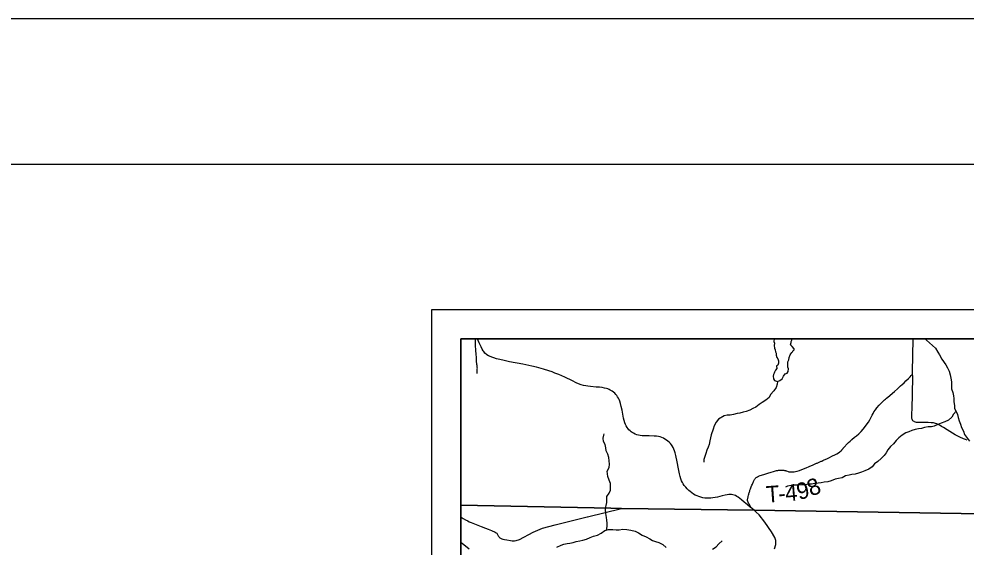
# Model space of a CAD drawing. Extents: x 0 to 34, y 0 to 22.
# Drawn here: x 21.997 to 25.254, y 20.183 to 22 of the extents above; entities that cross this region are included whole.
import ezdxf

# ---------------------------------------------------------------- set-up
doc = ezdxf.new("R2010")
doc.units = 0
for name, color, linetype in [('GM_X_Corporation', 7, 'Continuous'), ('GM_X_Minor_Lake', 7, 'Continuous'), ('GM_X_Minor_River', 7, 'Continuous'), ('GM_X_State_Route', 7, 'Continuous'), ('GM_X_Township_Road', 7, 'Continuous'), ('GM_X_Township_Road_Text', 7, 'Continuous'), ('SH_Border', 7, 'Continuous'), ('SH_Cut_Line', 7, 'Continuous'), ('SH_Data', 7, 'Continuous')]:
    doc.layers.add(name, color=color, linetype=linetype)

msp = doc.modelspace()

# ---------------------------------------------------------------- linework, layer by layer
at = {"layer": 'GM_X_Corporation'}
msp.add_lwpolyline([(27.1022, 20.9), (23.5167, 20.9), (23.5167, 20.3276), (24.0328, 20.3169), (24.0688, 20.3165), (24.5249, 20.3107), (25.4507, 20.2949), (26.2533, 20.2773), (26.5702, 20.276), (26.6351, 20.2734), (26.7196, 20.2707), (26.7822, 20.2704), (27.0031, 20.2673), (27.0873, 20.2665), (27.089, 20.3692), (27.0897, 20.4135), (27.0898, 20.417)], close=True, dxfattribs=at)
msp.add_lwpolyline([(27.1022, 20.9), (23.5167, 20.9), (23.5167, 20.3276), (24.0328, 20.3169), (24.0688, 20.3165), (24.5249, 20.3107), (25.4507, 20.2949), (26.2533, 20.2773), (26.5702, 20.276), (26.6351, 20.2734), (26.7196, 20.2707), (26.7822, 20.2704), (27.0031, 20.2673), (27.0873, 20.2665), (27.089, 20.3692), (27.0897, 20.4135), (27.0898, 20.417)], close=True, dxfattribs=at)
msp.add_lwpolyline([(27.0234, 16.6611), (27.0349, 17.5522), (27.0419, 17.8236), (27.0487, 18.5805), (27.0719, 19.3912), (27.0733, 19.498), (27.0761, 19.6806), (27.0864, 20.0138), (27.0885, 20.1139), (27.0907, 20.123), (27.0873, 20.2665), (27.0031, 20.2673), (26.7822, 20.2704), (26.7196, 20.2707), (26.6351, 20.2734), (26.5702, 20.276), (26.2533, 20.2773), (25.4507, 20.2949), (24.5249, 20.3107), (24.0688, 20.3165), (24.0328, 20.3169), (23.5167, 20.3276), (23.5167, 14.5642)], dxfattribs=at)
msp.add_lwpolyline([(27.0234, 16.6611), (27.0349, 17.5522), (27.0419, 17.8236), (27.0487, 18.5805), (27.0719, 19.3912), (27.0733, 19.498), (27.0761, 19.6806), (27.0864, 20.0138), (27.0885, 20.1139), (27.0907, 20.123), (27.0873, 20.2665), (27.0031, 20.2673), (26.7822, 20.2704), (26.7196, 20.2707), (26.6351, 20.2734), (26.5702, 20.276), (26.2533, 20.2773), (25.4507, 20.2949), (24.5249, 20.3107), (24.0688, 20.3165), (24.0328, 20.3169), (23.5167, 20.3276), (23.5167, 14.5642)], dxfattribs=at)
at = {"layer": 'GM_X_Minor_Lake'}
for points in [[(24.5943, 20.9), (24.593, 20.89), (24.5953, 20.8844), (24.5946, 20.8764), (24.5951, 20.8677), (24.597, 20.8613), (24.599, 20.8544), (24.6009, 20.8499), (24.6006, 20.8438), (24.603, 20.8359), (24.6072, 20.8303), (24.6091, 20.8238), (24.6092, 20.8163), (24.607, 20.809), (24.6036, 20.8063), (24.6021, 20.8052), (24.6033, 20.7972), (24.5992, 20.7915), (24.5948, 20.7853), (24.5937, 20.7815), (24.5918, 20.777), (24.5911, 20.7713), (24.5916, 20.7622), (24.5954, 20.7561), (24.6053, 20.7528)], [(24.6053, 20.7528), (24.614, 20.756), (24.6215, 20.7621), (24.6259, 20.7717), (24.6319, 20.7797), (24.6387, 20.781), (24.6417, 20.7867), (24.6431, 20.7966), (24.6415, 20.8019), (24.641, 20.8163), (24.6406, 20.8208), (24.6443, 20.8273), (24.6457, 20.8349), (24.649, 20.8441), (24.6513, 20.8475), (24.655, 20.8525), (24.6569, 20.8548), (24.6599, 20.8598), (24.6625, 20.8613), (24.6628, 20.8647), (24.6556, 20.8734), (24.6506, 20.8794), (24.6524, 20.8866), (24.6531, 20.8904), (24.6546, 20.895), (24.6552, 20.9)]]:
    msp.add_lwpolyline(points, dxfattribs=at)
at = {"layer": 'GM_X_Minor_River'}
for points in [[(25.113, 20.9), (25.1178, 20.8946), (25.1281, 20.8857), (25.1388, 20.8771), (25.1487, 20.8669), (25.1571, 20.8538), (25.1629, 20.844), (25.171, 20.83), (25.1841, 20.8105), (25.1899, 20.7999), (25.196, 20.7879), (25.1996, 20.7758), (25.2019, 20.764), (25.204, 20.7515), (25.2037, 20.7379), (25.2042, 20.728), (25.2089, 20.7155), (25.2109, 20.7034), (25.2114, 20.6939), (25.2115, 20.6829), (25.2139, 20.6697), (25.2147, 20.6602), (25.2201, 20.6497), (25.224, 20.6391), (25.2264, 20.6285), (25.2307, 20.6179), (25.2349, 20.6062), (25.2388, 20.5941), (25.245, 20.5817), (25.2489, 20.5703), (25.2654, 20.5478)], [(24.6053, 20.7528), (24.6039, 20.7433), (24.6006, 20.7327), (24.5924, 20.7212), (24.5815, 20.7078), (24.5767, 20.6975), (24.5658, 20.6882), (24.5527, 20.6808), (24.5422, 20.6735), (24.5316, 20.6646), (24.5207, 20.6603), (24.5109, 20.6538), (24.4981, 20.6498), (24.4879, 20.6474), (24.4766, 20.6439), (24.4664, 20.6422), (24.4547, 20.6398), (24.443, 20.637), (24.432, 20.6365), (24.4222, 20.6352), (24.4027, 20.6228), (24.3948, 20.6129), (24.3881, 20.6006), (24.3845, 20.5888), (24.3778, 20.569), (24.3749, 20.5591), (24.3724, 20.5484), (24.3702, 20.5366), (24.3669, 20.5264), (24.3629, 20.5161), (24.3588, 20.505), (24.3559, 20.4947), (24.3526, 20.4841), (24.3527, 20.4757)], [(25.2195, 20.6509), (25.2111, 20.6408), (25.2048, 20.6305), (25.1932, 20.6197), (25.1804, 20.6135), (25.1683, 20.6092), (25.157, 20.6045), (25.1446, 20.5994), (25.1348, 20.5974), (25.1238, 20.5972), (25.1109, 20.5944), (25.1011, 20.5909), (25.0902, 20.5904), (25.0785, 20.588), (25.0679, 20.5848), (25.057, 20.5797), (25.0464, 20.5762), (25.034, 20.5681), (25.0228, 20.5592), (25.0141, 20.5496), (25.004, 20.5388), (24.9939, 20.5296), (24.985, 20.5174), (24.9794, 20.5078), (24.9719, 20.4982), (24.9625, 20.4879), (24.9505, 20.4775), (24.9393, 20.4694), (24.9307, 20.4598), (24.9194, 20.4517), (24.9062, 20.4454), (24.8949, 20.4407), (24.884, 20.4372), (24.8723, 20.434), (24.8617, 20.4327), (24.8515, 20.4303), (24.8394, 20.4279), (24.8278, 20.4213), (24.8157, 20.4196), (24.8036, 20.4168), (24.7896, 20.4113), (24.7791, 20.4074), (24.7666, 20.4065), (24.7557, 20.4045), (24.7454, 20.4036), (24.7337, 20.4015), (24.7224, 20.4002), (24.7114, 20.3997), (24.7016, 20.3977), (24.688, 20.3975), (24.6766, 20.3963), (24.6623, 20.3961), (24.6524, 20.3948), (24.6396, 20.3928), (24.6328, 20.3896)], [(24.0147, 20.3169), (24.0167, 20.3267), (24.0183, 20.3369), (24.0187, 20.347), (24.0186, 20.3573), (24.0268, 20.3688), (24.0316, 20.3787), (24.0308, 20.3905), (24.0314, 20.4022), (24.0268, 20.4132), (24.0221, 20.4264), (24.0204, 20.4442), (24.0271, 20.4572), (24.0281, 20.469), (24.0265, 20.4796), (24.026, 20.4917), (24.0217, 20.5023), (24.0167, 20.514), (24.0154, 20.5246), (24.0126, 20.536), (24.0076, 20.5465), (24.0064, 20.5583), (24.0082, 20.5682), (24.0092, 20.5727)], [(24.0181, 20.2416), (24.0197, 20.2545), (24.02, 20.2651), (24.0192, 20.2754), (24.0177, 20.2849), (24.0154, 20.2986), (24.0146, 20.3115), (24.0147, 20.3169)], [(23.8472, 20.1825), (23.8612, 20.1901), (23.8707, 20.1932), (23.8821, 20.1955), (23.8915, 20.1971), (23.9033, 20.1994), (23.9132, 20.2025), (23.9257, 20.2048), (23.9359, 20.2071), (23.9484, 20.2106), (23.9613, 20.2159), (23.9727, 20.2205), (23.9863, 20.224), (23.9992, 20.2316), (24.0113, 20.2397), (24.0246, 20.2435), (24.039, 20.2432), (24.0508, 20.2421), (24.0607, 20.2429), (24.0743, 20.2452), (24.0872, 20.2441), (24.1009, 20.2415), (24.1161, 20.2374), (24.1279, 20.2321), (24.1408, 20.2238), (24.1541, 20.2185), (24.1666, 20.2121), (24.1761, 20.206), (24.1864, 20.2023), (24.1978, 20.1989), (24.2114, 20.1917), (24.2232, 20.1823)], [(23.5167, 20.2001), (23.5224, 20.1958), (23.5322, 20.1878), (23.5455, 20.1776)], [(24.3818, 20.176), (24.3943, 20.1844), (24.4042, 20.1947), (24.4148, 20.205)]]:
    msp.add_lwpolyline(points, dxfattribs=at)
at = {"layer": 'GM_X_State_Route'}
for points in [[(24.5145, 20.3186), (24.513, 20.3197), (24.5029, 20.328), (24.4912, 20.3382), (24.4823, 20.3459), (24.4765, 20.3505), (24.4709, 20.3544), (24.4657, 20.3576), (24.4608, 20.3601), (24.4562, 20.3618), (24.4515, 20.3631), (24.4473, 20.3637), (24.4437, 20.3639), (24.4388, 20.3638), (24.4327, 20.3631), (24.4261, 20.3619), (24.4152, 20.3592), (24.3995, 20.3552), (24.391, 20.3534), (24.383, 20.3522), (24.3761, 20.3515), (24.3699, 20.3513), (24.3624, 20.3514), (24.3555, 20.352), (24.3493, 20.3529), (24.342, 20.3547), (24.3354, 20.3568), (24.3291, 20.3594), (24.3228, 20.3623), (24.3169, 20.3657), (24.3106, 20.3698), (24.3051, 20.374), (24.3004, 20.378), (24.2951, 20.3833), (24.2901, 20.3889), (24.2851, 20.3953), (24.2816, 20.4005), (24.2784, 20.4059), (24.2757, 20.4115), (24.2729, 20.4185), (24.2707, 20.4257), (24.2684, 20.4354), (24.2651, 20.4519), (24.2604, 20.4769), (24.2561, 20.4982), (24.2538, 20.5072), (24.2516, 20.5142), (24.2492, 20.5205), (24.2465, 20.5261), (24.2435, 20.5314), (24.2407, 20.5355), (24.2377, 20.5393), (24.2334, 20.5437), (24.2288, 20.5477), (24.2239, 20.5514), (24.2187, 20.5547), (24.2133, 20.5576), (24.2082, 20.5599), (24.2025, 20.5619), (24.1965, 20.5634), (24.1899, 20.5645), (24.1813, 20.5651), (24.1645, 20.5656), (24.1465, 20.5659), (24.1403, 20.5663), (24.1334, 20.5671), (24.1273, 20.5684), (24.1218, 20.5699), (24.1165, 20.5719), (24.1108, 20.5745), (24.1064, 20.577), (24.1023, 20.5798), (24.0984, 20.583), (24.0948, 20.5866), (24.0916, 20.5904), (24.0883, 20.5951), (24.0854, 20.5999), (24.0832, 20.6045), (24.0807, 20.6109), (24.0784, 20.6181), (24.0764, 20.6266), (24.071, 20.654), (24.0682, 20.6667), (24.0655, 20.6769), (24.0629, 20.6852), (24.0607, 20.6909), (24.0583, 20.6959), (24.0555, 20.7006), (24.0528, 20.7046), (24.0497, 20.7084), (24.0458, 20.7123), (24.0417, 20.7159), (24.0367, 20.7195), (24.0305, 20.7234), (24.0262, 20.7256), (24.0223, 20.7272), (24.0171, 20.7288), (24.0106, 20.7304), (24.0027, 20.7319), (23.993, 20.7329), (23.9825, 20.7337), (23.9627, 20.7352), (23.9534, 20.7363), (23.9461, 20.7375), (23.9382, 20.7393), (23.9304, 20.7417), (23.9217, 20.745), (23.9131, 20.7487), (23.9002, 20.7549), (23.8741, 20.7678), (23.864, 20.7725), (23.8532, 20.7771), (23.8405, 20.782), (23.8306, 20.7855), (23.8189, 20.7894), (23.8011, 20.7948), (23.7772, 20.8016), (23.7611, 20.8059), (23.7508, 20.8083), (23.7295, 20.8125), (23.6837, 20.8209), (23.6654, 20.8246), (23.6509, 20.828), (23.6394, 20.8311), (23.6299, 20.834), (23.6234, 20.8363), (23.6153, 20.8396), (23.6114, 20.8416), (23.6065, 20.8446), (23.6036, 20.847), (23.5998, 20.8503), (23.5955, 20.8557), (23.5938, 20.8583), (23.5905, 20.8644), (23.5865, 20.872), (23.58, 20.8862), (23.5763, 20.8942), (23.5736, 20.9)], [(24.5251, 20.3101), (24.5194, 20.3149), (24.5145, 20.3186)], [(24.5953, 20.1775), (24.5993, 20.1917), (24.6004, 20.1987), (24.5998, 20.2058), (24.5969, 20.2163), (24.5849, 20.2359), (24.5615, 20.2694), (24.5427, 20.2943), (24.5326, 20.3034), (24.5251, 20.3101)]]:
    msp.add_lwpolyline(points, dxfattribs=at)
at = {"layer": 'GM_X_Township_Road'}
msp.add_line((23.9522, 20.2872), (24.069, 20.3159), dxfattribs=at)
for points in [[(23.5723, 20.7801), (23.573, 20.7891), (23.5732, 20.7926), (23.5734, 20.7952), (23.5735, 20.7981), (23.5734, 20.8008), (23.5731, 20.8042), (23.5728, 20.8071), (23.5725, 20.809), (23.5722, 20.8106), (23.572, 20.8119), (23.5718, 20.813), (23.5715, 20.8144), (23.5713, 20.8157), (23.5709, 20.8178), (23.5707, 20.8196), (23.5705, 20.821), (23.5704, 20.8226), (23.5704, 20.8242), (23.5703, 20.8258), (23.5703, 20.8271), (23.5703, 20.8291), (23.5701, 20.839), (23.5699, 20.8438), (23.5686, 20.8625), (23.5675, 20.8742), (23.567, 20.8842), (23.5669, 20.8923), (23.5671, 20.895), (23.5673, 20.8978), (23.5675, 20.8997), (23.5676, 20.9)], [(25.0702, 20.7781), (25.07, 20.79), (25.0703, 20.8087), (25.0704, 20.8192), (25.0708, 20.8316), (25.0711, 20.8459), (25.0712, 20.8515), (25.0714, 20.8658), (25.0716, 20.8745), (25.0716, 20.8825), (25.0717, 20.8875), (25.0718, 20.8966), (25.0719, 20.8997), (25.0719, 20.9)], [(24.5145, 20.3186), (24.5125, 20.3231), (24.5116, 20.325), (24.51, 20.3277), (24.5082, 20.3309), (24.5058, 20.3345), (24.5044, 20.3372), (24.5034, 20.3401), (24.5028, 20.3432), (24.5028, 20.3448), (24.5028, 20.3469), (24.5029, 20.3486), (24.5032, 20.3506), (24.5037, 20.3529), (24.5042, 20.3554), (24.5048, 20.3576), (24.5059, 20.3616), (24.5067, 20.3647), (24.5074, 20.3671), (24.5082, 20.37), (24.5089, 20.3727), (24.51, 20.3761), (24.5109, 20.3788), (24.5117, 20.3817), (24.5126, 20.384), (24.5139, 20.3874), (24.5152, 20.3908), (24.5173, 20.396), (24.5191, 20.4), (24.5202, 20.4028), (24.5214, 20.4055), (24.5226, 20.4086), (24.5239, 20.4109), (24.5252, 20.4135), (24.5264, 20.4153), (24.5275, 20.4172), (24.5288, 20.4188), (24.5304, 20.4204), (24.5321, 20.4221), (24.5341, 20.4236), (24.5368, 20.4252), (24.5401, 20.4268), (24.5459, 20.429), (24.5589, 20.4331), (24.572, 20.437), (24.5762, 20.4382), (24.5809, 20.4396), (24.5951, 20.4441), (24.6017, 20.4461), (24.605, 20.4468), (24.6071, 20.4471), (24.609, 20.4474), (24.6119, 20.4477), (24.6148, 20.4478), (24.618, 20.4479), (24.622, 20.4479), (24.6244, 20.4478), (24.6269, 20.4475), (24.6297, 20.4471), (24.6326, 20.4464), (24.6344, 20.4458), (24.637, 20.445), (24.6422, 20.4434), (24.6451, 20.4426), (24.6482, 20.442), (24.6528, 20.4416), (24.6576, 20.4416), (24.663, 20.442), (24.6672, 20.4428), (24.6732, 20.4443), (24.6809, 20.4467), (24.689, 20.4497), (24.7045, 20.4562), (24.7147, 20.4607), (24.7284, 20.4666), (24.7396, 20.4714), (24.7419, 20.4724), (24.7441, 20.4734), (24.7469, 20.4746), (24.7491, 20.4756), (24.7509, 20.4764), (24.7531, 20.4773), (24.7554, 20.4783), (24.7576, 20.4793), (24.7616, 20.4811), (24.7666, 20.4834), (24.7748, 20.4872), (24.7798, 20.4894), (24.7841, 20.4915), (24.7925, 20.4957), (24.797, 20.4979), (24.8002, 20.4995), (24.8048, 20.5018), (24.8093, 20.5045), (24.8148, 20.5077), (24.8196, 20.511), (24.8227, 20.5134), (24.8254, 20.5157), (24.8269, 20.5172), (24.8278, 20.5182), (24.8285, 20.5191), (24.8292, 20.52), (24.8302, 20.5211), (24.831, 20.5221), (24.8318, 20.5232), (24.8328, 20.5245), (24.8354, 20.5276), (24.8378, 20.5303), (24.8394, 20.5319), (24.8409, 20.5337), (24.8434, 20.5363), (24.8465, 20.5393), (24.8498, 20.5429), (24.8552, 20.5481), (24.8584, 20.5511), (24.8612, 20.5536), (24.8704, 20.5608), (24.8767, 20.5657), (24.885, 20.5723), (24.8891, 20.576), (24.8934, 20.5805), (24.9006, 20.5891), (24.9083, 20.5988), (24.9141, 20.6068), (24.9182, 20.613), (24.923, 20.621), (24.9313, 20.6369), (24.934, 20.6425), (24.9354, 20.6452), (24.9373, 20.6484), (24.9421, 20.6555), (24.9471, 20.6618), (24.9557, 20.6715), (24.9582, 20.6743), (24.9623, 20.6788), (24.9663, 20.6826), (24.974, 20.6897), (24.9767, 20.6921), (24.98, 20.6949), (24.9852, 20.6992), (24.9914, 20.7043), (25.0009, 20.7122), (25.0074, 20.7179), (25.0182, 20.7278), (25.0286, 20.7374), (25.0345, 20.7427), (25.0408, 20.7486), (25.0474, 20.755), (25.0557, 20.7633), (25.0613, 20.7691), (25.0656, 20.7735), (25.0702, 20.7781)], [(25.2577, 20.551), (25.2518, 20.5529), (25.2449, 20.5556), (25.2329, 20.5609), (25.2234, 20.5656), (25.2169, 20.5691), (25.2073, 20.5748), (25.1889, 20.5864), (25.1763, 20.5944), (25.17, 20.5983), (25.1652, 20.6012), (25.1586, 20.6046), (25.1534, 20.6068), (25.1488, 20.6084), (25.1454, 20.6093), (25.1421, 20.6101), (25.1385, 20.6106), (25.1342, 20.6109), (25.1236, 20.6112), (25.1106, 20.6114), (25.0957, 20.6116), (25.0907, 20.6118), (25.0876, 20.6119), (25.0839, 20.6122), (25.0802, 20.6129), (25.0772, 20.6137), (25.075, 20.6147), (25.0729, 20.6162), (25.0712, 20.6179), (25.0698, 20.6199), (25.0685, 20.6227), (25.0678, 20.6251), (25.0674, 20.6275), (25.0673, 20.6294), (25.0672, 20.6312), (25.0672, 20.6343), (25.0676, 20.6411), (25.0678, 20.6448), (25.068, 20.6479), (25.0684, 20.6529), (25.0687, 20.6597), (25.0692, 20.6771), (25.0693, 20.692), (25.0695, 20.7087), (25.0697, 20.7299), (25.0706, 20.7497), (25.0708, 20.7634), (25.0706, 20.7708), (25.0702, 20.7781)], [(23.5167, 20.2869), (23.5174, 20.2864), (23.5248, 20.282), (23.5326, 20.2775), (23.5405, 20.273), (23.5456, 20.2704), (23.5517, 20.2679), (23.569, 20.2607), (23.5865, 20.2539), (23.6016, 20.248), (23.6107, 20.2443), (23.6222, 20.2398), (23.6344, 20.2349), (23.6384, 20.2327), (23.6406, 20.2307), (23.6422, 20.2284), (23.6456, 20.2224), (23.6472, 20.2193), (23.649, 20.2171), (23.6509, 20.2153), (23.6529, 20.2137), (23.6553, 20.2122), (23.6577, 20.2111), (23.6612, 20.2101), (23.6669, 20.2091), (23.6747, 20.208), (23.6875, 20.2057), (23.6937, 20.2051), (23.7013, 20.2052), (23.7069, 20.206), (23.7179, 20.2098), (23.7649, 20.2348), (23.798, 20.2482), (23.841, 20.26), (23.9512, 20.287), (23.9522, 20.2872)]]:
    msp.add_lwpolyline(points, dxfattribs=at)
at = {"layer": 'SH_Border'}
msp.add_lwpolyline([(1.5, 21.5), (33.5, 21.5), (33.5, 0.5), (1.5, 0.5)], close=True, dxfattribs=at)
at = {"layer": 'SH_Cut_Line'}
msp.add_lwpolyline([(0, 0), (34, 0), (34, 22), (0, 22)], close=True, dxfattribs=at)
at = {"layer": 'SH_Data'}
for points in [[(23.4167, 21), (30.4167, 21), (30.4167, 14), (23.4167, 14)], [(23.5167, 20.9), (30.3167, 20.9), (30.3167, 14.1), (23.5167, 14.1)]]:
    msp.add_lwpolyline(points, close=True, dxfattribs=at)

# ---------------------------------------------------------------- texts
at = {"layer": 'GM_X_Township_Road_Text'}
for s, rotation, p in [('8', 22.4005, (24.7215, 20.3564)), ('T', 4.1885, (24.5679, 20.3358)), ('4', 4.4909, (24.6339, 20.3407)), ('9', 14.0921, (24.679, 20.3451)), ('-', 4.2457, (24.6103, 20.3389))]:
    msp.add_text(s, height=0.0568, rotation=rotation, dxfattribs=at).set_placement(p)

doc.saveas('drawing.dxf')
